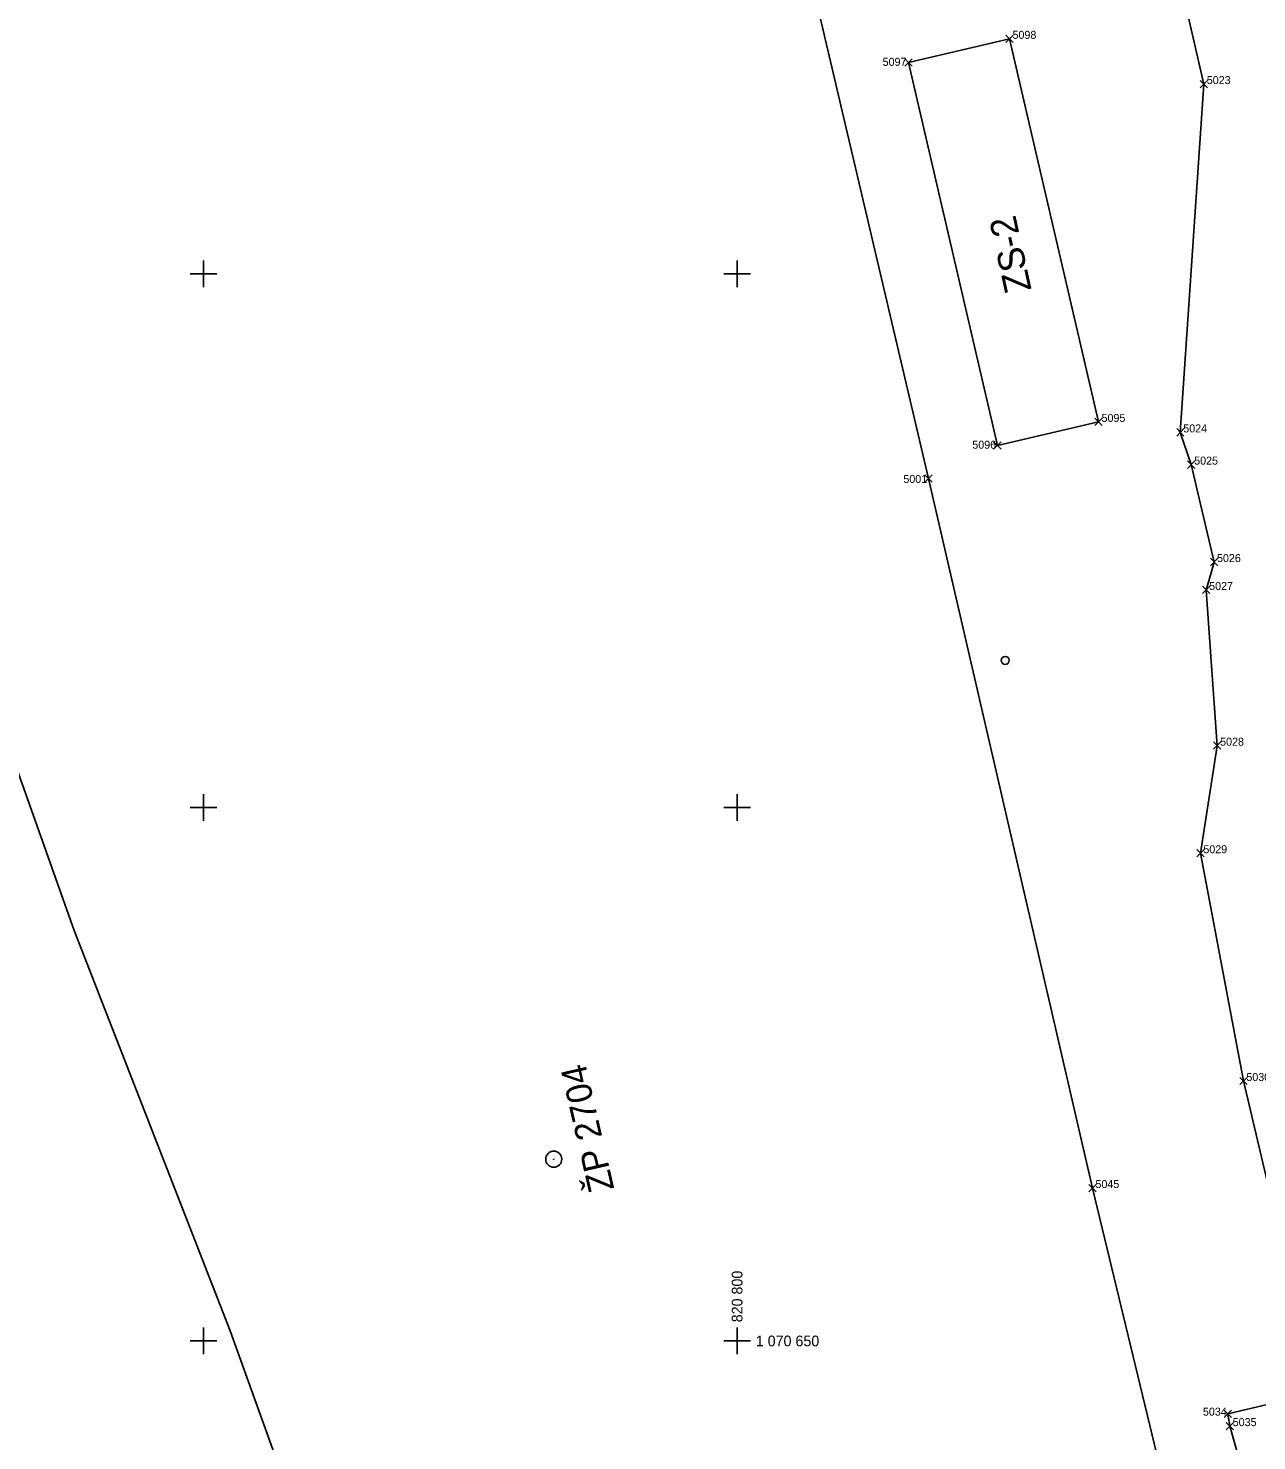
# Model space of a CAD drawing. Extents: x -821172 to -820632, y -1070921 to -1069931.
# Drawn here: x -820866.4 to -820751.3, y -1070659.4 to -1070527 of the extents above; entities that cross this region are included whole.
import ezdxf

# ---------------------------------------------------------------- set-up
doc = ezdxf.new("R2010")
doc.units = 0
for name, color, linetype in [('Sit', 7, 'Continuous'), ('Sttaniceni a namezniky', 7, 'Continuous'), ('VB_bod_DZ', 7, 'Continuous'), ('Vrstva 52', 7, 'Continuous'), ('Vrstva 53', 7, 'Continuous'), ('Vrstva 55', 7, 'Continuous'), ('ZBP', 7, 'Continuous')]:
    doc.layers.add(name, color=color, linetype=linetype)

msp = doc.modelspace()

# ---------------------------------------------------------------- linework, layer by layer
at = {"layer": 'Sit'}
for p, q in [((-820850, -1070548.75), (-820850, -1070550)), ((-820800, -1070548.75), (-820800, -1070550)), ((-820851.25, -1070550), (-820850, -1070550)), ((-820848.75, -1070550), (-820850, -1070550)), ((-820850, -1070551.25), (-820850, -1070550)), ((-820801.25, -1070550), (-820800, -1070550)), ((-820798.75, -1070550), (-820800, -1070550)), ((-820800, -1070551.25), (-820800, -1070550)), ((-820850, -1070598.75), (-820850, -1070600)), ((-820800, -1070598.75), (-820800, -1070600)), ((-820851.25, -1070600), (-820850, -1070600)), ((-820848.75, -1070600), (-820850, -1070600)), ((-820850, -1070601.25), (-820850, -1070600)), ((-820801.25, -1070600), (-820800, -1070600)), ((-820798.75, -1070600), (-820800, -1070600)), ((-820800, -1070601.25), (-820800, -1070600)), ((-820850, -1070648.75), (-820850, -1070650)), ((-820800, -1070648.75), (-820800, -1070650)), ((-820851.25, -1070650), (-820850, -1070650)), ((-820848.75, -1070650), (-820850, -1070650)), ((-820850, -1070651.25), (-820850, -1070650)), ((-820801.25, -1070650), (-820800, -1070650)), ((-820798.75, -1070650), (-820800, -1070650)), ((-820800, -1070651.25), (-820800, -1070650))]:
    msp.add_line(p, q, dxfattribs=at)
at = {"layer": 'Sttaniceni a namezniky'}
msp.add_circle((-820774.87, -1070586.23), 0.375, dxfattribs=at)
at = {"layer": 'VB_bod_DZ'}
for p, q in [((-820774.81, -1070528.32), (-820774.12, -1070527.63)), ((-820774.12, -1070528.32), (-820774.81, -1070527.63)), ((-820784.29, -1070530.54), (-820783.6, -1070529.85)), ((-820783.6, -1070530.54), (-820784.29, -1070529.85)), ((-820756.62, -1070532.56), (-820755.93, -1070531.87)), ((-820755.93, -1070532.56), (-820756.62, -1070531.87)), ((-820766.48, -1070564.22), (-820765.79, -1070563.54)), ((-820765.79, -1070564.22), (-820766.48, -1070563.54)), ((-820775.96, -1070566.44), (-820775.27, -1070565.75)), ((-820775.27, -1070566.44), (-820775.96, -1070565.75)), ((-820758.81, -1070565.2), (-820758.13, -1070564.51)), ((-820758.13, -1070565.2), (-820758.81, -1070564.51)), ((-820757.79, -1070568.23), (-820757.11, -1070567.54)), ((-820757.11, -1070568.23), (-820757.79, -1070567.54)), ((-820782.41, -1070569.53), (-820781.72, -1070568.85)), ((-820781.72, -1070569.53), (-820782.41, -1070568.85)), ((-820755.65, -1070577.35), (-820754.97, -1070576.66)), ((-820754.97, -1070577.35), (-820755.65, -1070576.66)), ((-820756.39, -1070579.97), (-820755.7, -1070579.28)), ((-820755.7, -1070579.97), (-820756.39, -1070579.28)), ((-820755.36, -1070594.56), (-820754.67, -1070593.87)), ((-820754.67, -1070594.56), (-820755.36, -1070593.87)), ((-820756.93, -1070604.64), (-820756.25, -1070603.95)), ((-820756.25, -1070604.64), (-820756.93, -1070603.95)), ((-820752.9, -1070625.98), (-820752.22, -1070625.3)), ((-820752.22, -1070625.98), (-820752.9, -1070625.3)), ((-820767.04, -1070636.02), (-820766.35, -1070635.33)), ((-820766.35, -1070636.02), (-820767.04, -1070635.33)), ((-820754.37, -1070657.18), (-820753.68, -1070656.49)), ((-820753.68, -1070657.18), (-820754.37, -1070656.49)), ((-820754.18, -1070658.32), (-820753.49, -1070657.64)), ((-820753.49, -1070658.32), (-820754.18, -1070657.64))]:
    msp.add_line(p, q, dxfattribs=at)
at = {"layer": 'Vrstva 52'}
for points in [[(-820782.06, -1070569.19), (-820823.93, -1070391.03)], [(-820791.18, -1070389.77), (-820780.82, -1070405.78), (-820777.68, -1070442.4), (-820774.11, -1070459), (-820761.04, -1070511.47), (-820756.27, -1070532.22), (-820758.47, -1070564.86)], [(-820758.47, -1070564.86), (-820757.45, -1070567.88), (-820755.31, -1070577.01), (-820756.05, -1070579.63), (-820755.02, -1070594.22), (-820756.59, -1070604.3), (-820752.56, -1070625.64), (-820745.66, -1070654.88), (-820746.96, -1070655.19), (-820749.11, -1070655.68), (-820754.03, -1070656.83), (-820753.84, -1070657.98), (-820750.47, -1070669.89)], [(-820755.08, -1070683.79), (-820766.7, -1070635.67), (-820782.06, -1070569.19)]]:
    msp.add_lwpolyline(points, dxfattribs=at)
msp.add_lwpolyline([(-820766.13, -1070563.88), (-820775.61, -1070566.1), (-820783.95, -1070530.19), (-820774.47, -1070527.98)], close=True, dxfattribs=at)
at = {"layer": 'Vrstva 53'}
msp.add_lwpolyline([(-820793.34, -1070807.43), (-820797.89, -1070798.01), (-820802.49, -1070786.9), (-820807.86, -1070771.6), (-820839.34, -1070671.73), (-820847.49, -1070649.05), (-820862.12, -1070611.55), (-820870.18, -1070588.9), (-820893.88, -1070513.71), (-820901.78, -1070488.65), (-820908.48, -1070465.88), (-820912.77, -1070441.75), (-820907.91, -1070440.8), (-820914.43, -1070404.83), (-820920.34, -1070372.85), (-820926.76, -1070341.17), (-820933.59, -1070313.73), (-820939.94, -1070294.5), (-820946.33, -1070279.59), (-820953.63, -1070265.09), (-820959.73, -1070254.91)], dxfattribs=at)
at = {"layer": 'Vrstva 55'}
msp.add_lwpolyline([(-820793.34, -1070807.43), (-820797.89, -1070798.01), (-820802.49, -1070786.9), (-820807.86, -1070771.6), (-820839.34, -1070671.73), (-820847.49, -1070649.05), (-820862.12, -1070611.55), (-820870.18, -1070588.9), (-820893.88, -1070513.71), (-820901.78, -1070488.65), (-820908.48, -1070465.88), (-820912.77, -1070441.75), (-820907.91, -1070440.8), (-820914.43, -1070404.83), (-820920.34, -1070372.85), (-820926.76, -1070341.17), (-820933.59, -1070313.73), (-820939.94, -1070294.5), (-820946.33, -1070279.59), (-820953.63, -1070265.09), (-820959.73, -1070254.91)], dxfattribs=at)
at = {"layer": 'ZBP'}
msp.add_line((-820817.16, -1070633.02), (-820817.19, -1070632.92), dxfattribs=at)
msp.add_circle((-820817.18, -1070632.97), 0.756, dxfattribs=at)

# ---------------------------------------------------------------- texts
at = {"layer": 'Sit'}
msp.add_text('820 800', height=1, rotation=90, dxfattribs=at).set_placement((-820799.5, -1070648.25))
msp.add_text('1 070 650', height=1, dxfattribs=at).set_placement((-820798.25, -1070650.5))
at = {"layer": 'VB_bod_DZ'}
for s, p in [(' 5098', (-820774.47, -1070527.98)), (' 5097', (-820786.64, -1070530.51)), (' 5023', (-820756.27, -1070532.22)), (' 5095', (-820766.13, -1070563.88)), (' 5024', (-820758.47, -1070564.86)), (' 5096', (-820778.24, -1070566.39)), (' 5025', (-820757.45, -1070567.88)), (' 5001', (-820784.7, -1070569.6)), (' 5026', (-820755.31, -1070577.01)), (' 5027', (-820756.05, -1070579.63)), (' 5028', (-820755.02, -1070594.22)), (' 5029', (-820756.59, -1070604.3)), (' 5030', (-820752.56, -1070625.64)), (' 5045', (-820766.7, -1070635.67)), (' 5034', (-820756.63, -1070657)), (' 5035', (-820753.84, -1070657.98))]:
    msp.add_text(s, height=0.75, dxfattribs=at).set_placement(p)
at = {"layer": 'Vrstva 52'}
msp.add_text('ZS-2', height=2.5, rotation=102.2938, dxfattribs=at).set_placement((-820772.4, -1070551.48))
at = {"layer": 'ZBP'}
msp.add_text('ŽP 2704', height=2.4, rotation=103, dxfattribs=at).set_placement((-820811.5, -1070635.74))

doc.saveas('drawing.dxf')
